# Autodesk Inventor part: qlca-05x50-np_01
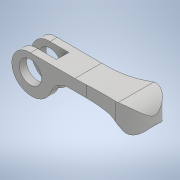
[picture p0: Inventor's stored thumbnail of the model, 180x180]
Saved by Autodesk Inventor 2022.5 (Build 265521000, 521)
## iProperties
Part Number: qlca-05x50-np_01
Material: 一般
Document SubType Name: Modeling
Designer: ImaoCorp
Density: 1 g/cm^3
Appearance: 既定
Author: ImaoCorp
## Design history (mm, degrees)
feature "qlca-05x50-np_01"
node "ソリッド1"
